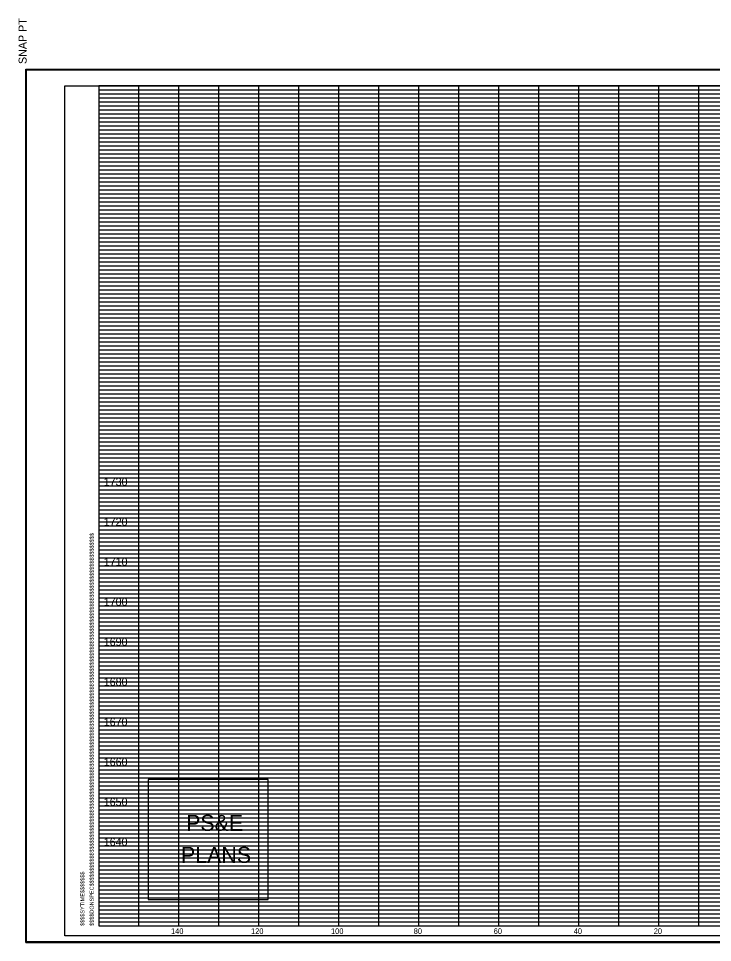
# Model space of a CAD drawing. Extents: x 980 to 2228, y 978 to 2394.
# Drawn here: x 979.9 to 1153.4, y 1535.9 to 1766.8 of the extents above; entities that cross this region are included whole.
import ezdxf

# ---------------------------------------------------------------- set-up
doc = ezdxf.new("R2010")
doc.units = 0
for name, color, linetype in [('DESIGN - SHEET - Corner Text', 7, 'Continuous'), ('DESIGN - SHEET - Light Grid', 7, 'Continuous'), ('DESIGN - SHEET - Linework', 7, 'Continuous'), ('DESIGN - SHEET - Plot Shape', 7, 'Continuous'), ('DESIGN - TYPICAL - Finished Grade and Subgrade', 7, 'Continuous')]:
    doc.layers.add(name, color=color, linetype=linetype)

# ---------------------------------------------------------------- blocks, each defined once
blk = doc.blocks.new('XSTSHT')
at = {"layer": 'DESIGN - SHEET - Light Grid'}
for p, q in [((0, 20.9), (8, 20.9)), ((0, 20.8), (8, 20.8)), ((8, 20.9), (16, 20.9)), ((8, 20.8), (16, 20.8)), ((0, 20.7), (8, 20.7)), ((0, 20.6), (8, 20.6)), ((8, 20.7), (16, 20.7)), ((8, 20.6), (16, 20.6)), ((0, 20.5), (8, 20.5)), ((0, 20.4), (8, 20.4)), ((8, 20.5), (16, 20.5)), ((8, 20.4), (16, 20.4)), ((0, 20.3), (8, 20.3)), ((0, 20.2), (8, 20.2)), ((0, 20.1), (8, 20.1)), ((8, 20.3), (16, 20.3)), ((8, 20.2), (16, 20.2)), ((8, 20.1), (16, 20.1)), ((0, 19.9), (8, 19.9)), ((8, 19.9), (16, 19.9)), ((0, 19.8), (8, 19.8)), ((0, 19.7), (8, 19.7)), ((8, 19.8), (16, 19.8)), ((8, 19.7), (16, 19.7)), ((0, 19.6), (8, 19.6)), ((0, 19.5), (8, 19.5)), ((0, 19.4), (8, 19.4)), ((8, 19.6), (16, 19.6)), ((8, 19.5), (16, 19.5)), ((8, 19.4), (16, 19.4)), ((0, 19.3), (8, 19.3)), ((0, 19.2), (8, 19.2)), ((8, 19.3), (16, 19.3)), ((8, 19.2), (16, 19.2)), ((0, 19.1), (8, 19.1)), ((8, 19.1), (16, 19.1)), ((0, 18.9), (8, 18.9)), ((0, 18.8), (8, 18.8)), ((8, 18.9), (16, 18.9)), ((8, 18.8), (16, 18.8)), ((0, 18.7), (8, 18.7)), ((0, 18.6), (8, 18.6)), ((0, 18.5), (8, 18.5)), ((8, 18.7), (16, 18.7)), ((8, 18.6), (16, 18.6)), ((8, 18.5), (16, 18.5)), ((0, 18.4), (8, 18.4)), ((0, 18.3), (8, 18.3)), ((8, 18.4), (16, 18.4)), ((8, 18.3), (16, 18.3)), ((0, 18.2), (8, 18.2)), ((0, 18.1), (8, 18.1)), ((8, 18.2), (16, 18.2)), ((8, 18.1), (16, 18.1)), ((0, 17.9), (8, 17.9)), ((0, 17.8), (8, 17.8)), ((8, 17.9), (16, 17.9)), ((8, 17.8), (16, 17.8)), ((0, 17.7), (8, 17.7)), ((0, 17.6), (8, 17.6)), ((8, 17.7), (16, 17.7)), ((8, 17.6), (16, 17.6)), ((0, 17.5), (8, 17.5)), ((0, 17.4), (8, 17.4)), ((8, 17.5), (16, 17.5)), ((8, 17.4), (16, 17.4)), ((0, 17.3), (8, 17.3)), ((0, 17.2), (8, 17.2)), ((0, 17.1), (8, 17.1)), ((8, 17.3), (16, 17.3)), ((8, 17.2), (16, 17.2)), ((8, 17.1), (16, 17.1)), ((0, 16.9), (8, 16.9)), ((8, 16.9), (16, 16.9)), ((0, 16.8), (8, 16.8)), ((0, 16.7), (8, 16.7)), ((8, 16.8), (16, 16.8)), ((8, 16.7), (16, 16.7)), ((0, 16.6), (8, 16.6)), ((0, 16.5), (8, 16.5)), ((0, 16.4), (8, 16.4)), ((8, 16.6), (16, 16.6)), ((8, 16.5), (16, 16.5)), ((8, 16.4), (16, 16.4)), ((0, 16.3), (8, 16.3)), ((0, 16.2), (8, 16.2)), ((8, 16.3), (16, 16.3)), ((8, 16.2), (16, 16.2)), ((0, 16.1), (8, 16.1)), ((8, 16.1), (16, 16.1)), ((0, 15.9), (8, 15.9)), ((0, 15.8), (8, 15.8)), ((8, 15.9), (16, 15.9)), ((8, 15.8), (16, 15.8)), ((0, 15.7), (8, 15.7)), ((0, 15.6), (8, 15.6)), ((0, 15.5), (8, 15.5)), ((8, 15.7), (16, 15.7)), ((8, 15.6), (16, 15.6)), ((8, 15.5), (16, 15.5)), ((0, 15.4), (8, 15.4)), ((0, 15.3), (8, 15.3)), ((8, 15.4), (16, 15.4)), ((8, 15.3), (16, 15.3)), ((0, 15.2), (8, 15.2)), ((0, 15.1), (8, 15.1)), ((8, 15.2), (16, 15.2)), ((8, 15.1), (16, 15.1)), ((0, 14.9), (8, 14.9)), ((0, 14.8), (8, 14.8)), ((8, 14.9), (16, 14.9)), ((8, 14.8), (16, 14.8)), ((0, 14.7), (8, 14.7)), ((0, 14.6), (8, 14.6)), ((8, 14.7), (16, 14.7)), ((8, 14.6), (16, 14.6)), ((0, 14.5), (8, 14.5)), ((0, 14.4), (8, 14.4)), ((8, 14.5), (16, 14.5)), ((8, 14.4), (16, 14.4)), ((0, 14.3), (8, 14.3)), ((0, 14.2), (8, 14.2)), ((0, 14.1), (8, 14.1)), ((8, 14.3), (16, 14.3)), ((8, 14.2), (16, 14.2)), ((8, 14.1), (16, 14.1)), ((0, 13.9), (8, 13.9)), ((8, 13.9), (16, 13.9)), ((0, 13.8), (8, 13.8)), ((0, 13.7), (8, 13.7)), ((8, 13.8), (16, 13.8)), ((8, 13.7), (16, 13.7)), ((0, 13.6), (8, 13.6)), ((0, 13.5), (8, 13.5)), ((0, 13.4), (8, 13.4)), ((8, 13.6), (16, 13.6)), ((8, 13.5), (16, 13.5)), ((8, 13.4), (16, 13.4)), ((0, 13.3), (8, 13.3)), ((0, 13.2), (8, 13.2)), ((8, 13.3), (16, 13.3)), ((8, 13.2), (16, 13.2)), ((0, 13.1), (8, 13.1)), ((8, 13.1), (16, 13.1)), ((0, 12.9), (8, 12.9)), ((0, 12.8), (8, 12.8)), ((8, 12.9), (16, 12.9)), ((8, 12.8), (16, 12.8)), ((0, 12.7), (8, 12.7)), ((0, 12.6), (8, 12.6)), ((0, 12.5), (8, 12.5)), ((8, 12.7), (16, 12.7)), ((8, 12.6), (16, 12.6)), ((8, 12.5), (16, 12.5)), ((0, 12.4), (8, 12.4)), ((0, 12.3), (8, 12.3)), ((8, 12.4), (16, 12.4)), ((8, 12.3), (16, 12.3)), ((0, 12.2), (8, 12.2)), ((0, 12.1), (8, 12.1)), ((8, 12.2), (16, 12.2)), ((8, 12.1), (16, 12.1)), ((0, 11.9), (8, 11.9)), ((0, 11.8), (8, 11.8)), ((8, 11.9), (16, 11.9)), ((8, 11.8), (16, 11.8)), ((0, 11.7), (8, 11.7)), ((0, 11.6), (8, 11.6)), ((8, 11.7), (16, 11.7)), ((8, 11.6), (16, 11.6)), ((0, 11.5), (8, 11.5)), ((0, 11.4), (8, 11.4)), ((8, 11.5), (16, 11.5)), ((8, 11.4), (16, 11.4)), ((0, 11.3), (8, 11.3)), ((0, 11.2), (8, 11.2)), ((0, 11.1), (8, 11.1)), ((8, 11.3), (16, 11.3)), ((8, 11.2), (16, 11.2)), ((8, 11.1), (16, 11.1)), ((0, 10.9), (8, 10.9)), ((8, 10.9), (16, 10.9)), ((0, 10.8), (8, 10.8)), ((0, 10.7), (8, 10.7)), ((8, 10.8), (16, 10.8)), ((8, 10.7), (16, 10.7)), ((0, 10.6), (8, 10.6)), ((0, 10.5), (8, 10.5)), ((0, 10.4), (8, 10.4)), ((8, 10.6), (16, 10.6)), ((8, 10.5), (16, 10.5)), ((8, 10.4), (16, 10.4)), ((0, 10.3), (8, 10.3)), ((0, 10.2), (8, 10.2)), ((8, 10.3), (16, 10.3)), ((8, 10.2), (16, 10.2)), ((0, 10.1), (8, 10.1)), ((8, 10.1), (16, 10.1)), ((0, 9.9), (8, 9.9)), ((0, 9.8), (8, 9.8)), ((0, 9.7), (8, 9.7)), ((8, 9.9), (16, 9.9)), ((8, 9.8), (16, 9.8)), ((8, 9.7), (16, 9.7)), ((0, 9.6), (8, 9.6)), ((0, 9.5), (8, 9.5)), ((8, 9.6), (16, 9.6)), ((8, 9.5), (16, 9.5)), ((0, 9.4), (8, 9.4)), ((0, 9.3), (8, 9.3)), ((8, 9.4), (16, 9.4)), ((8, 9.3), (16, 9.3)), ((0, 9.2), (8, 9.2)), ((0, 9.1), (8, 9.1)), ((8, 9.2), (16, 9.2)), ((8, 9.1), (16, 9.1)), ((0, 8.9), (8, 8.9)), ((0, 8.8), (8, 8.8)), ((8, 8.9), (16, 8.9)), ((8, 8.8), (16, 8.8)), ((0, 8.7), (8, 8.7)), ((0, 8.6), (8, 8.6)), ((8, 8.7), (16, 8.7)), ((8, 8.6), (16, 8.6)), ((0, 8.5), (8, 8.5)), ((0, 8.4), (8, 8.4)), ((8, 8.5), (16, 8.5)), ((8, 8.4), (16, 8.4)), ((0, 8.3), (8, 8.3)), ((0, 8.2), (8, 8.2)), ((0, 8.1), (8, 8.1)), ((8, 8.3), (16, 8.3)), ((8, 8.2), (16, 8.2)), ((8, 8.1), (16, 8.1)), ((0, 7.9), (8, 7.9)), ((8, 7.9), (16, 7.9)), ((0, 7.8), (8, 7.8)), ((0, 7.7), (8, 7.7)), ((8, 7.8), (16, 7.8)), ((8, 7.7), (16, 7.7)), ((0, 7.6), (8, 7.6)), ((0, 7.5), (8, 7.5)), ((0, 7.4), (8, 7.4)), ((8, 7.6), (16, 7.6)), ((8, 7.5), (16, 7.5)), ((8, 7.4), (16, 7.4)), ((0, 7.3), (8, 7.3)), ((0, 7.2), (8, 7.2)), ((8, 7.3), (16, 7.3)), ((8, 7.2), (16, 7.2)), ((0, 7.1), (8, 7.1)), ((8, 7.1), (16, 7.1)), ((0, 6.9), (8, 6.9)), ((0, 6.8), (8, 6.8)), ((0, 6.7), (8, 6.7)), ((8, 6.9), (16, 6.9)), ((8, 6.8), (16, 6.8)), ((8, 6.7), (16, 6.7)), ((0, 6.6), (8, 6.6)), ((0, 6.5), (8, 6.5)), ((8, 6.6), (16, 6.6)), ((8, 6.5), (16, 6.5)), ((0, 6.4), (8, 6.4)), ((0, 6.3), (8, 6.3)), ((8, 6.4), (16, 6.4)), ((8, 6.3), (16, 6.3)), ((0, 6.2), (8, 6.2)), ((0, 6.1), (8, 6.1)), ((8, 6.2), (16, 6.2)), ((8, 6.1), (16, 6.1)), ((0, 5.9), (8, 5.9)), ((0, 5.8), (8, 5.8)), ((8, 5.9), (16, 5.9)), ((8, 5.8), (16, 5.8)), ((0, 5.7), (8, 5.7)), ((0, 5.6), (8, 5.6)), ((8, 5.7), (16, 5.7)), ((8, 5.6), (16, 5.6)), ((0, 5.5), (8, 5.5)), ((0, 5.4), (8, 5.4)), ((8, 5.5), (16, 5.5)), ((8, 5.4), (16, 5.4)), ((0, 5.3), (8, 5.3)), ((0, 5.2), (8, 5.2)), ((0, 5.1), (8, 5.1)), ((8, 5.3), (16, 5.3)), ((8, 5.2), (16, 5.2)), ((8, 5.1), (16, 5.1)), ((0, 4.9), (8, 4.9)), ((8, 4.9), (16, 4.9)), ((0, 4.8), (8, 4.8)), ((0, 4.7), (8, 4.7)), ((8, 4.8), (16, 4.8)), ((8, 4.7), (16, 4.7)), ((0, 4.6), (8, 4.6)), ((0, 4.5), (8, 4.5)), ((0, 4.4), (8, 4.4)), ((8, 4.6), (16, 4.6)), ((8, 4.5), (16, 4.5)), ((8, 4.4), (16, 4.4)), ((0, 4.3), (8, 4.3)), ((0, 4.2), (8, 4.2)), ((8, 4.3), (16, 4.3)), ((8, 4.2), (16, 4.2)), ((0, 4.1), (8, 4.1)), ((8, 4.1), (16, 4.1)), ((0, 3.9), (8, 3.9)), ((0, 3.8), (8, 3.8)), ((0, 3.7), (8, 3.7)), ((8, 3.9), (16, 3.9)), ((8, 3.8), (16, 3.8)), ((8, 3.7), (16, 3.7)), ((0, 3.6), (8, 3.6)), ((0, 3.5), (8, 3.5)), ((8, 3.6), (16, 3.6)), ((8, 3.5), (16, 3.5)), ((0, 3.4), (8, 3.4)), ((0, 3.3), (8, 3.3)), ((8, 3.4), (16, 3.4)), ((8, 3.3), (16, 3.3)), ((0, 3.2), (8, 3.2)), ((0, 3.1), (8, 3.1)), ((8, 3.2), (16, 3.2)), ((8, 3.1), (16, 3.1)), ((0, 2.9), (8, 2.9)), ((0, 2.8), (8, 2.8)), ((8, 2.9), (16, 2.9)), ((8, 2.8), (16, 2.8)), ((0, 2.7), (8, 2.7)), ((0, 2.6), (8, 2.6)), ((8, 2.7), (16, 2.7)), ((8, 2.6), (16, 2.6)), ((0, 2.5), (8, 2.5)), ((0, 2.4), (8, 2.4)), ((8, 2.5), (16, 2.5)), ((8, 2.4), (16, 2.4)), ((0, 2.3), (8, 2.3)), ((0, 2.2), (8, 2.2)), ((0, 2.1), (8, 2.1)), ((8, 2.3), (16, 2.3)), ((8, 2.2), (16, 2.2)), ((8, 2.1), (16, 2.1)), ((0, 1.9), (8, 1.9)), ((8, 1.9), (16, 1.9)), ((0, 1.8), (8, 1.8)), ((0, 1.7), (8, 1.7)), ((8, 1.8), (16, 1.8)), ((8, 1.7), (16, 1.7)), ((0, 1.6), (8, 1.6)), ((0, 1.5), (8, 1.5)), ((0, 1.4), (8, 1.4)), ((8, 1.6), (16, 1.6)), ((8, 1.5), (16, 1.5)), ((8, 1.4), (16, 1.4)), ((0, 1.3), (8, 1.3)), ((0, 1.2), (8, 1.2)), ((8, 1.3), (16, 1.3)), ((8, 1.2), (16, 1.2)), ((0, 1.1), (8, 1.1)), ((8, 1.1), (16, 1.1)), ((0, 0.9), (8, 0.9)), ((0, 0.8), (8, 0.8)), ((0, 0.7), (8, 0.7)), ((8, 0.9), (16, 0.9)), ((8, 0.8), (16, 0.8)), ((8, 0.7), (16, 0.7)), ((0, 0.6), (8, 0.6)), ((0, 0.5), (8, 0.5)), ((8, 0.6), (16, 0.6)), ((8, 0.5), (16, 0.5)), ((0, 0.4), (8, 0.4)), ((0, 0.3), (8, 0.3)), ((8, 0.4), (16, 0.4)), ((8, 0.3), (16, 0.3)), ((0, 0.2), (8, 0.2)), ((0, 0.1), (8, 0.1)), ((8, 0.2), (16, 0.2)), ((8, 0.1), (16, 0.1))]:
    blk.add_line(p, q, dxfattribs=at)
at = {"layer": 'DESIGN - SHEET - Linework'}
for p, q in [((-1.823, -0.414), (-1.823, 21.414)), ((-1.823, 21.414), (32.217, 21.414)), ((1, 0), (1, 21)), ((2, 0), (2, 21)), ((3, 0), (3, 21)), ((4, 0), (4, 21)), ((5, 0), (5, 21)), ((6, 0), (6, 21)), ((7, 0), (7, 21)), ((8, 0), (8, 21)), ((9, 0), (9, 21)), ((10, 0), (10, 21)), ((11, 0), (11, 21)), ((12, 0), (12, 21)), ((13, 0), (13, 21)), ((14, 0), (14, 21)), ((15, 0), (15, 21)), ((0, 20), (28, 20)), ((0, 19), (32, 19)), ((0, 18), (32, 18)), ((0, 17), (32, 17)), ((0, 16), (32, 16)), ((0, 15), (32, 15)), ((0, 14), (32, 14)), ((0, 13), (32, 13)), ((0, 12), (32, 12)), ((0, 11), (32, 11)), ((0, 10), (32, 10)), ((0, 9), (32, 9)), ((0, 8), (32, 8)), ((0, 7), (32, 7)), ((0, 6), (32, 6)), ((0, 5), (32, 5)), ((0, 4), (32, 4)), ((0, 3), (32, 3)), ((0, 2), (32, 2)), ((0, 1), (32, 1)), ((-1.823, -0.414), (32.217, -0.414))]:
    blk.add_line(p, q, dxfattribs=at)
blk.add_lwpolyline([(0, 21), (0, 0), (32, 0), (32, 21), (0, 21)], dxfattribs=at)
at = {"layer": 'DESIGN - SHEET - Plot Shape'}
for points in [[(-1.803, 21.394), (32.197, 21.394), (32.197, -0.394), (-1.803, -0.394)], [(-0.85, 21), (32, 21), (32, -0.25), (-0.85, -0.25)]]:
    blk.add_lwpolyline(points, close=True, dxfattribs=at)
at = {"layer": 'DESIGN - SHEET - Corner Text'}
for s, height, p in [('  SNAP PT', 0.2, (-1.803, 21.394)), ('$$$$DGNSPEC$$$$$$$$$$$$$$$$$$$$$$$$$$$$$$$$$$$$$$$$$$$$$$$$$$$$$$$$$$$$$$$$$$$$$$$$$$$$$$$$$$$$$$$$$$$$$$$$$$$$$$$$$$$$$$$$$$$', 0.100002, (-0.126, 0)), ('$$$$SYTIME$$$$$$$', 0.1, (-0.358, 0))]:
    blk.add_text(s, height=height, rotation=90, dxfattribs=at).set_placement(p)

msp = doc.modelspace()

# ---------------------------------------------------------------- linework, layer by layer
at = {"layer": 'DESIGN - SHEET - Corner Text'}
msp.add_lwpolyline([(1012.33, 1576.58), (1012.33, 1546.58), (1042.33, 1546.58), (1042.33, 1576.58)], close=True, dxfattribs=at)
at = {"layer": 'DESIGN - SHEET - Plot Shape'}
msp.add_lwpolyline([(991.5, 1750), (1320, 1750), (1320, 1537.5), (991.5, 1537.5)], close=True, dxfattribs=at)

# ---------------------------------------------------------------- block references
at = {"layer": 'DESIGN - TYPICAL - Finished Grade and Subgrade', "xscale": 10, "yscale": 10}
msp.add_blockref('XSTSHT', (1000, 1540), dxfattribs=at)

# ---------------------------------------------------------------- texts
at = {"layer": 'DESIGN - SHEET - Corner Text'}
for s, height, p in [('1730', 2, (1001.25, 1650)), ('1720', 2, (1001.25, 1640)), ('1710', 2, (1001.25, 1630)), ('1700', 2, (1001.25, 1620)), ('1690', 2, (1001.25, 1610)), ('1680', 2, (1001.25, 1600)), ('1670', 2, (1001.25, 1590)), ('1660', 2, (1001.25, 1580)), ('1650', 2, (1001.25, 1570)), ('PS&E', 4, (1021.84, 1563.76)), ('1640', 2, (1001.25, 1560)), ('PLANS', 4, (1020.56, 1555.76)), ('140', 1.4, (1018.06, 1538)), ('120', 1.4, (1038.06, 1538)), ('100', 1.4, (1058.06, 1538)), ('80', 1.4, (1078.74, 1538)), ('60', 1.4, (1098.74, 1538)), ('40', 1.4, (1118.74, 1538)), ('20', 1.4, (1138.74, 1538))]:
    msp.add_text(s, height=height, dxfattribs=at).set_placement(p)

doc.saveas('drawing.dxf')
